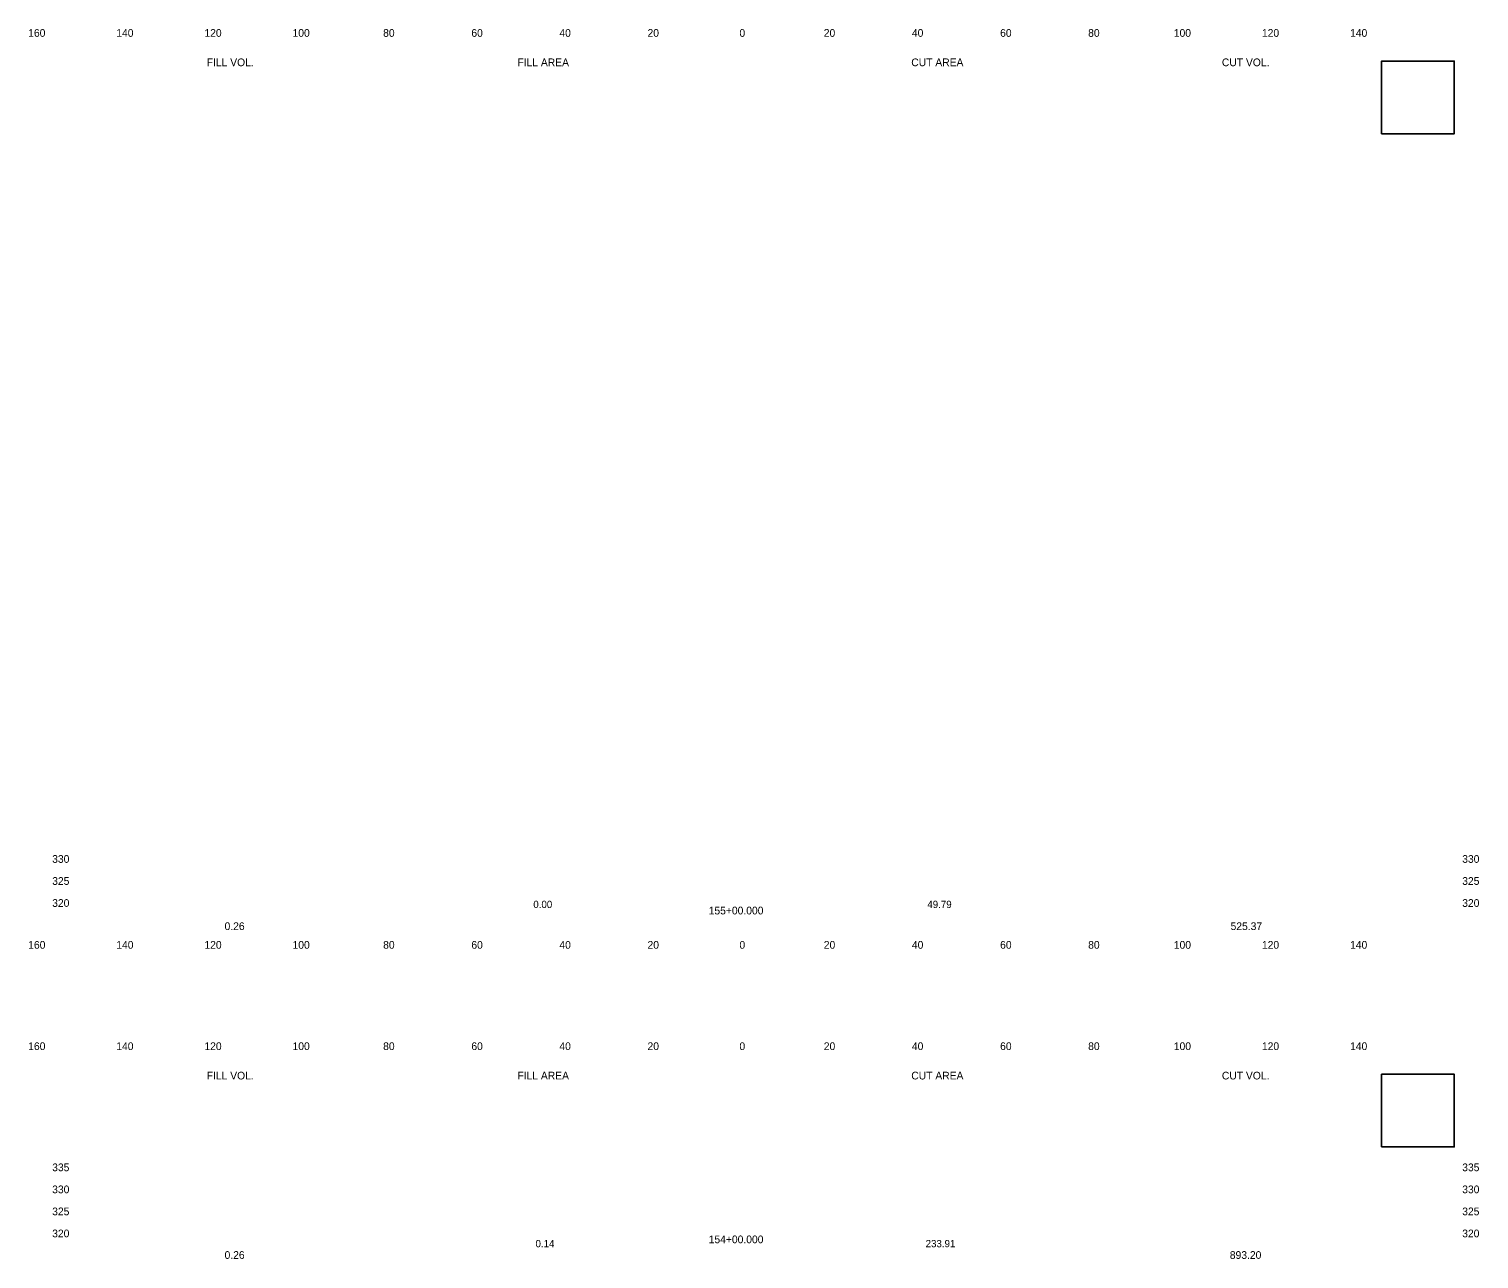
# Model space of a CAD drawing. Extents: x 21477 to 21806, y 6470 to 11049.
# Drawn here: x 21477.1 to 21806.1, y 10769.9 to 11049.1 of the extents above; entities that cross this region are included whole.
import ezdxf

# ---------------------------------------------------------------- set-up
doc = ezdxf.new("R2010")
doc.units = 0
for name, color, linetype in [('SHEET_CONSULTANT_STAMP', 7, 'Continuous'), ('XS_SHEET_EW_TX_AREA', 7, 'Continuous'), ('XS_SHEET_EW_TX_VOLUME', 7, 'Continuous'), ('XS_SHEET_LABELS_ELEVATION', 7, 'Continuous'), ('XS_SHEET_LABELS_OFFSET', 7, 'Continuous'), ('XS_SHEET_LABELS_STATION', 7, 'Continuous'), ('XS_SHEET_TX', 7, 'Continuous')]:
    doc.layers.add(name, color=color, linetype=linetype)

msp = doc.modelspace()

# ---------------------------------------------------------------- linework, layer by layer
at = {"layer": 'SHEET_CONSULTANT_STAMP'}
for points in [[(21784.04, 11025.34), (21800.54, 11025.34), (21800.54, 11041.84), (21784.04, 11041.84)], [(21784.04, 10795.34), (21800.54, 10795.34), (21800.54, 10811.84), (21784.04, 10811.84)]]:
    msp.add_lwpolyline(points, close=True, dxfattribs=at)

# ---------------------------------------------------------------- texts
at = {"layer": 'XS_SHEET_EW_TX_AREA'}
for s, p in [(' 0.00 ', (21590.92, 10849.58)), (' 49.79 ', (21680.34, 10849.58)), (' 0.14 ', (21591.42, 10772.58)), (' 233.91 ', (21679.95, 10772.58))]:
    msp.add_text(s, height=1.65, dxfattribs=at).set_placement(p)
at = {"layer": 'XS_SHEET_EW_TX_VOLUME'}
for s, p in [(' 0.26 ', (21520.81, 10844.58)), (' 525.37 ', (21749.12, 10844.58)), (' 0.26 ', (21520.81, 10769.94)), (' 893.20 ', (21748.95, 10769.94))]:
    msp.add_text(s, height=1.75, dxfattribs=at).set_placement(p)
at = {"layer": 'XS_SHEET_LABELS_ELEVATION'}
for s, p in [('  330  ', (21481.04, 10859.84)), ('  330  ', (21801.04, 10859.84)), ('  325  ', (21481.04, 10854.84)), ('  325  ', (21801.04, 10854.84)), ('  320  ', (21481.04, 10849.84)), ('  320  ', (21801.04, 10849.84)), ('  335  ', (21481.04, 10789.84)), ('  335  ', (21801.04, 10789.84)), ('  330  ', (21481.04, 10784.84)), ('  330  ', (21801.04, 10784.84)), ('  325  ', (21481.04, 10779.84)), ('  325  ', (21801.04, 10779.84)), ('  320  ', (21481.04, 10774.84)), ('  320  ', (21801.04, 10774.84))]:
    msp.add_text(s, height=1.75, dxfattribs=at).set_placement(p)
at = {"layer": 'XS_SHEET_LABELS_OFFSET'}
for s, p in [('  160  ', (21475.6, 11047.34)), ('  140  ', (21495.59, 11047.34)), ('  120  ', (21515.59, 11047.34)), ('  100  ', (21535.59, 11047.34)), ('  80  ', (21556.15, 11047.34)), ('  60  ', (21576.17, 11047.34)), ('  40  ', (21596.15, 11047.34)), ('  20  ', (21616.15, 11047.34)), ('  0  ', (21637.01, 11047.34)), ('  0  ', (21637.01, 11047.34)), ('  20  ', (21656.15, 11047.34)), ('  40  ', (21676.15, 11047.34)), ('  60  ', (21696.17, 11047.34)), ('  80  ', (21716.15, 11047.34)), ('  100  ', (21735.59, 11047.34)), ('  120  ', (21755.59, 11047.34)), ('  140  ', (21775.59, 11047.34)), ('  160  ', (21475.6, 10840.34)), ('  140  ', (21495.59, 10840.34)), ('  120  ', (21515.59, 10840.34)), ('  100  ', (21535.59, 10840.34)), ('  80  ', (21556.15, 10840.34)), ('  60  ', (21576.17, 10840.34)), ('  40  ', (21596.15, 10840.34)), ('  20  ', (21616.15, 10840.34)), ('  0  ', (21637.01, 10840.34)), ('  0  ', (21637.01, 10840.34)), ('  20  ', (21656.15, 10840.34)), ('  40  ', (21676.15, 10840.34)), ('  60  ', (21696.17, 10840.34)), ('  80  ', (21716.15, 10840.34)), ('  100  ', (21735.59, 10840.34)), ('  120  ', (21755.59, 10840.34)), ('  140  ', (21775.59, 10840.34)), ('  160  ', (21475.6, 10817.34)), ('  140  ', (21495.59, 10817.34)), ('  120  ', (21515.59, 10817.34)), ('  100  ', (21535.59, 10817.34)), ('  80  ', (21556.15, 10817.34)), ('  60  ', (21576.17, 10817.34)), ('  40  ', (21596.15, 10817.34)), ('  20  ', (21616.15, 10817.34)), ('  0  ', (21637.01, 10817.34)), ('  0  ', (21637.01, 10817.34)), ('  20  ', (21656.15, 10817.34)), ('  40  ', (21676.15, 10817.34)), ('  60  ', (21696.17, 10817.34)), ('  80  ', (21716.15, 10817.34)), ('  100  ', (21735.59, 10817.34)), ('  120  ', (21755.59, 10817.34)), ('  140  ', (21775.59, 10817.34))]:
    msp.add_text(s, height=1.75, dxfattribs=at).set_placement(p)
at = {"layer": 'XS_SHEET_LABELS_STATION'}
for s, p in [('  155+00.000  ', (21630.03, 10848.13)), ('  154+00.000  ', (21630.03, 10773.49))]:
    msp.add_text(s, height=1.75, dxfattribs=at).set_placement(p)
at = {"layer": 'XS_SHEET_TX'}
for s, p in [('FILL VOL.', (21517.41, 11040.67)), ('FILL AREA', (21587.92, 11040.67)), ('CUT AREA', (21677.31, 11040.67)), ('CUT VOL.', (21747.8, 11040.67)), ('FILL VOL.', (21517.41, 10810.67)), ('FILL AREA', (21587.92, 10810.67)), ('CUT AREA', (21677.31, 10810.67)), ('CUT VOL.', (21747.8, 10810.67))]:
    msp.add_text(s, height=1.75, dxfattribs=at).set_placement(p)

doc.saveas('drawing.dxf')
